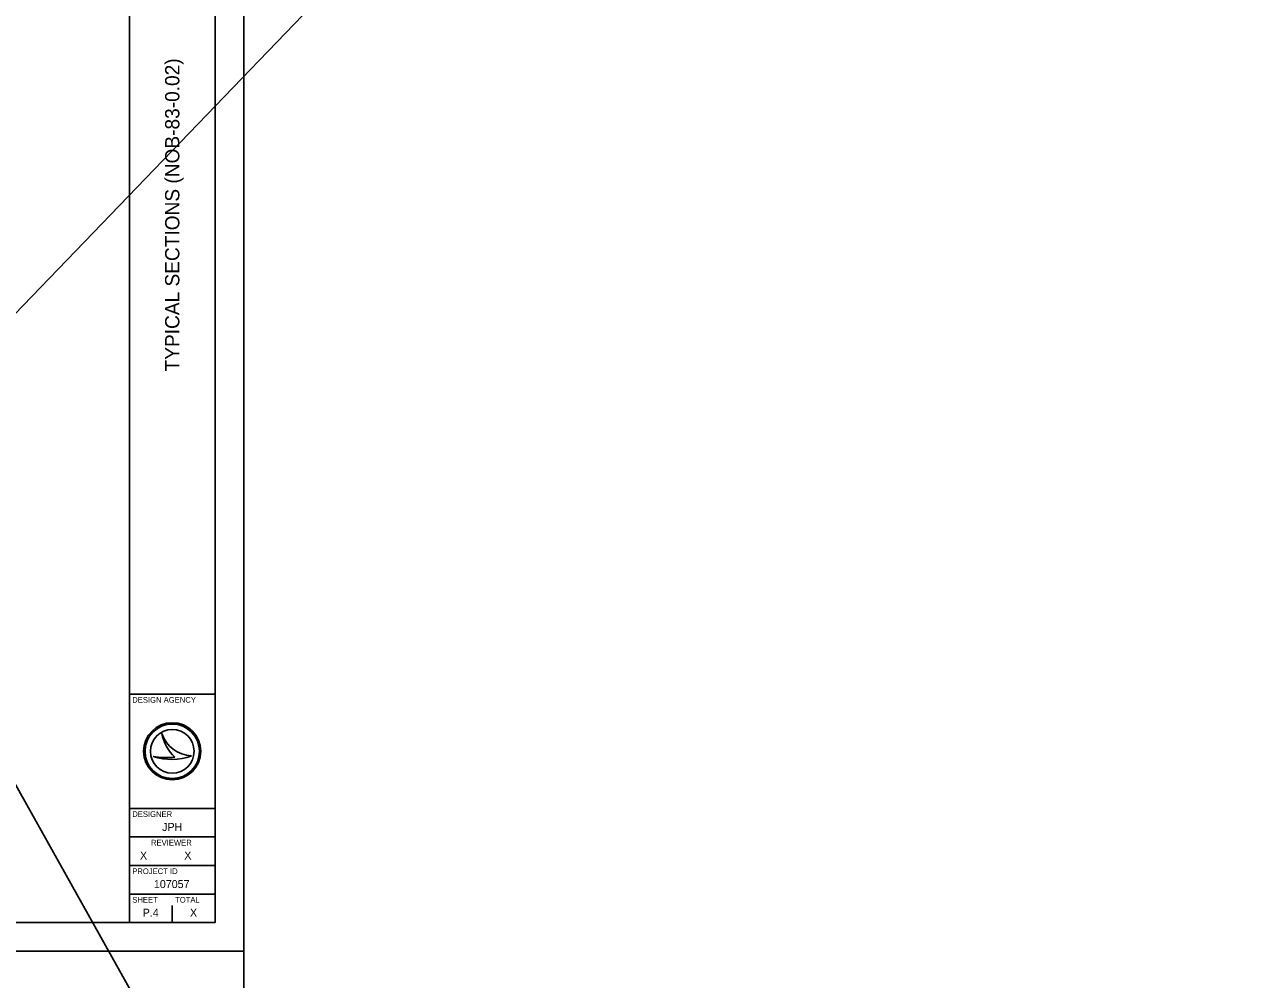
# Model space of a CAD drawing. Extents: x -396 to 156, y -166 to 172.
# Drawn here: x -268.4 to -204, y -66 to -15.8 of the extents above; entities that cross this region are included whole.
import ezdxf

# ---------------------------------------------------------------- set-up
doc = ezdxf.new("R2010")
doc.units = 0
for name, color, linetype in [('SH_Border', 7, 'Continuous'), ('SH_Cut_Line', 7, 'Continuous'), ('SH_Data', 7, 'Continuous'), ('XS_P_Finished_Grade', 7, 'Continuous')]:
    doc.layers.add(name, color=color, linetype=linetype)

msp = doc.modelspace()

# ---------------------------------------------------------------- linework, layer by layer
at = {"layer": 'SH_Border'}
for p, q in [((-262.902, -62.996), (-262.902, 0.004)), ((-262.902, -50.996), (-258.402, -50.996)), ((-262.902, -56.996), (-258.402, -56.996)), ((-262.902, -58.496), (-258.402, -58.496)), ((-262.902, -59.996), (-258.402, -59.996)), ((-262.902, -61.496), (-258.402, -61.496))]:
    msp.add_line(p, q, dxfattribs=at)
msp.add_lwpolyline([(-354.402, 0.004), (-258.402, 0.004), (-258.402, -62.996), (-354.402, -62.996)], close=True, dxfattribs=at)
at = {"layer": 'SH_Cut_Line'}
for points in [[(-358.902, -64.496), (-256.902, -64.496), (-256.902, 1.504), (-358.902, 1.504)], [(-358.902, -130.496), (-256.902, -130.496), (-256.902, -64.496), (-358.902, -64.496)]]:
    msp.add_lwpolyline(points, close=True, dxfattribs=at)
at = {"layer": 'SH_Data'}
for p, q in [((-261.2, -53.067), (-261.2, -53.067)), ((-260.652, -53.996), (-260.652, -53.996)), ((-261.65, -54.267), (-261.65, -54.267)), ((-259.64, -54.24), (-259.64, -54.24)), ((-260.652, -62.996), (-260.652, -62.096)), ((-261.777, -62.471), (-261.777, -62.471))]:
    msp.add_line(p, q, dxfattribs=at)
for radius in [1.5, 1.43, 1.43, 1.147]:
    msp.add_circle((-260.652, -53.996), radius, dxfattribs=at)
for centre, radius, start, end in [((-259.554, -52.503), 1.74, 198.92567, 198.93195), ((-258.862, -52.585), 2.387, 191.63793, 191.64215), ((-259.554, -52.503), 1.74, 198.93195, 267.16574), ((-258.862, -52.585), 2.387, 191.64215, 226.09467), ((-260.684, -51.386), 3.039, 251.45764, 290.08324), ((-260.958, -50.532), 3.798, 259.49639, 259.49952), ((-260.684, -51.386), 3.039, 251.45274, 251.45764), ((-260.958, -50.532), 3.798, 259.49952, 276.66723)]:
    msp.add_arc(centre, radius, start, end, dxfattribs=at)
at = {"layer": 'XS_P_Finished_Grade'}
for p, q in [((-396.097, 171.685), (-207.077, -166.247)), ((-88.939, 155.921), (-374.438, -140.631))]:
    msp.add_line(p, q, dxfattribs=at)

# ---------------------------------------------------------------- texts
at = {"layer": 'SH_Data'}
msp.add_text('TYPICAL SECTIONS (NOB-83-0.02)', height=0.75, rotation=90, dxfattribs=at).set_placement((-260.277, -34.046))
for s, height, p in [('DESIGN AGENCY', 0.3, (-262.752, -51.446)), ('DESIGNER', 0.3, (-262.752, -57.446)), ('JPH', 0.42, (-261.183, -58.181)), ('REVIEWER', 0.3, (-261.767, -58.946)), ('X', 0.42, (-262.346, -59.681)), ('X', 0.42, (-260.021, -59.681)), ('PROJECT ID', 0.3, (-262.752, -60.446)), ('107057', 0.42, (-261.617, -61.181)), ('SHEET', 0.3, (-262.752, -61.946)), ('TOTAL', 0.3, (-260.502, -61.946)), ('P.4', 0.42, (-262.203, -62.681)), ('X', 0.42, (-259.721, -62.681))]:
    msp.add_text(s, height=height, dxfattribs=at).set_placement(p)

doc.saveas('drawing.dxf')
